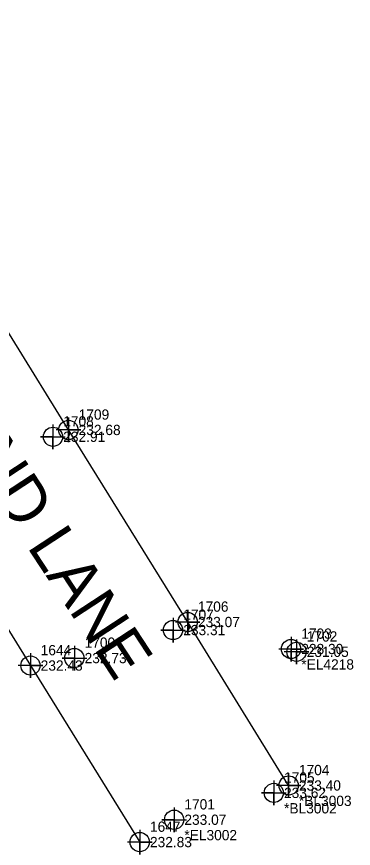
# Model space of a CAD drawing. Extents: x 2130621 to 2131998, y 642516 to 644503.
# Drawn here: x 2131203.6 to 2131285.6, y 643834.2 to 644036.8 of the extents above; entities that cross this region are included whole.
import ezdxf

# ---------------------------------------------------------------- set-up
doc = ezdxf.new("R2010")
doc.units = 0
for name, color, linetype in [('Exist Roads EOP', 7, 'Continuous'), ('Exist Roads EOP Other Cogo Comment', 7, 'Continuous'), ('Exist Roads EOP Other Cogo Elevation', 7, 'Continuous'), ('Exist Roads EOP Other Cogo Number', 7, 'Continuous'), ('Exist Roads EOP Other Cogo Point CELL', 7, 'Continuous'), ('Exist Roads EOT Cogo Comment', 7, 'Continuous'), ('Exist Roads EOT Cogo Elevation', 7, 'Continuous'), ('Exist Roads EOT Cogo Number', 7, 'Continuous'), ('Exist Roads EOT Cogo Point CELL', 7, 'Continuous'), ('Exist Roads EOT Text', 7, 'Continuous'), ('Exist Structure Minor Drop Inlet Cogo Elevation', 7, 'Continuous'), ('Exist Structure Minor Drop Inlet Cogo Number', 7, 'Continuous'), ('Exist Structure Minor Drop Inlet Cogo Point CELL', 7, 'Continuous'), ('Exist Structure Minor Pipes RCP 18 Inch Cogo Comment', 7, 'Continuous'), ('Exist Structure Minor Pipes RCP 18 Inch Cogo Elevation', 7, 'Continuous'), ('Exist Structure Minor Pipes RCP 18 Inch Cogo Number', 7, 'Continuous'), ('Exist Structure Minor Pipes RCP 18 Inch Cogo Point CELL', 7, 'Continuous'), ('Prop Horizontal Alignment', 7, 'Continuous')]:
    doc.layers.add(name, color=color, linetype=linetype)

msp = doc.modelspace()

# ---------------------------------------------------------------- linework, layer by layer
at = {"layer": 'Exist Roads EOP'}
for points in [[(2131269.83, 643849.54), (2131245.23, 643889.35), (2131216.18, 643936.13), (2131188.66, 643980.63), (2131160.56, 644026.02), (2131133.77, 644069.38), (2131106.56, 644113.29), (2131078.46, 644158.69), (2131052.15, 644201.1)], [(2131125, 644001.4), (2131151.48, 643966.59), (2131158.59, 643957.1), (2131179.44, 643923.18), (2131206.93, 643878.75), (2131233.55, 643835.75)]]:
    msp.add_lwpolyline(points, dxfattribs=at)
msp.add_spline([(2131166.25, 643216.7), (2131171.81, 643218.72), (2131182.37, 643223.97), (2131191.81, 643231.15), (2131200.5, 643239.7), (2131208.81, 643249.07), (2131216.07, 643259), (2131218.72, 643264.35), (2131220.54, 643270.1), (2131222.84, 643282.01), (2131224.36, 643293.92), (2131224.88, 643317.79), (2131222.06, 643367.67), (2131218.54, 643416.81), (2131214.32, 643466.35), (2131209.17, 643515.67), (2131202.79, 643565.15), (2131195.05, 643613.99), (2131186.4, 643662.48), (2131176.01, 643711.41), (2131164.62, 643759.89), (2131151.87, 643807.85), (2131137.86, 643855.41), (2131122.57, 643902.86), (2131105.96, 643949.49), (2131091.53, 643988.04)], degree=3, dxfattribs=at)
at = {"layer": 'Exist Roads EOP Other Cogo Point CELL'}
for points in [[(2131216.18, 643939.13), (2131216.18, 643933.13), (2131216.18, 643936.13), (2131219.18, 643936.13), (2131213.18, 643936.13)], [(2131245.23, 643892.35), (2131245.23, 643886.35), (2131245.23, 643889.35), (2131248.23, 643889.35), (2131242.23, 643889.35)], [(2131206.93, 643881.75), (2131206.93, 643875.75), (2131206.93, 643878.75), (2131209.93, 643878.75), (2131203.93, 643878.75)], [(2131269.83, 643852.54), (2131269.83, 643846.54), (2131269.83, 643849.54), (2131272.83, 643849.54), (2131266.83, 643849.54)], [(2131233.55, 643838.75), (2131233.55, 643832.75), (2131233.55, 643835.75), (2131236.55, 643835.75), (2131230.55, 643835.75)]]:
    msp.add_lwpolyline(points, dxfattribs=at)
for centre in [(2131216.18, 643936.13), (2131245.23, 643889.35), (2131206.93, 643878.75), (2131269.83, 643849.54), (2131233.55, 643835.75)]:
    msp.add_circle(centre, 2.34, dxfattribs=at)
at = {"layer": 'Exist Roads EOT Cogo Point CELL'}
for points in [[(2131212.42, 643937.47), (2131212.42, 643931.47), (2131212.42, 643934.47), (2131209.42, 643934.47), (2131215.42, 643934.47)], [(2131241.66, 643890.39), (2131241.66, 643884.39), (2131241.66, 643887.39), (2131238.66, 643887.39), (2131244.66, 643887.39)], [(2131217.63, 643883.57), (2131217.63, 643877.57), (2131217.63, 643880.57), (2131214.63, 643880.57), (2131220.63, 643880.57)], [(2131266.21, 643850.73), (2131266.21, 643844.73), (2131266.21, 643847.73), (2131263.21, 643847.73), (2131269.21, 643847.73)], [(2131241.93, 643844.19), (2131241.93, 643838.19), (2131241.93, 643841.19), (2131238.93, 643841.19), (2131244.93, 643841.19)]]:
    msp.add_lwpolyline(points, dxfattribs=at)
for centre in [(2131212.42, 643934.47), (2131241.66, 643887.39), (2131217.63, 643880.57), (2131266.21, 643847.73), (2131241.93, 643841.19)]:
    msp.add_circle(centre, 2.34, dxfattribs=at)
at = {"layer": 'Exist Structure Minor Drop Inlet Cogo Point CELL'}
msp.add_lwpolyline([(2131271.74, 643885.09), (2131271.74, 643879.09), (2131271.74, 643882.09), (2131274.74, 643882.09), (2131268.74, 643882.09)], dxfattribs=at)
msp.add_circle((2131271.74, 643882.09), 2.34, dxfattribs=at)
at = {"layer": 'Exist Structure Minor Pipes RCP 18 Inch Cogo Point CELL'}
msp.add_lwpolyline([(2131270.41, 643885.77), (2131270.41, 643879.77), (2131270.41, 643882.77), (2131273.41, 643882.77), (2131267.41, 643882.77)], dxfattribs=at)
msp.add_circle((2131270.41, 643882.77), 2.34, dxfattribs=at)
at = {"layer": 'Prop Horizontal Alignment'}
msp.add_arc((2129448.47, 643307.66), 1788.96, 4.14306, 22.49968, dxfattribs=at)

# ---------------------------------------------------------------- texts
at = {"layer": 'Exist Roads EOP Other Cogo Comment'}
msp.add_text('*BL3003', height=2.5, dxfattribs=at).set_placement((2131272.33, 643844.54))
at = {"layer": 'Exist Roads EOP Other Cogo Elevation'}
for s, p in [('232.68', (2131218.68, 643934.88)), ('233.07', (2131247.73, 643888.1)), ('232.43', (2131209.43, 643877.5)), ('233.40', (2131272.33, 643848.29)), ('232.83', (2131236.05, 643834.5))]:
    msp.add_text(s, height=2.5, dxfattribs=at).set_placement(p)
at = {"layer": 'Exist Roads EOP Other Cogo Number'}
for s, p in [('1709', (2131218.68, 643938.63)), ('1706', (2131247.73, 643891.85)), ('1644', (2131209.43, 643881.25)), ('1704', (2131272.33, 643852.04)), ('1647', (2131236.05, 643838.25))]:
    msp.add_text(s, height=2.5, dxfattribs=at).set_placement(p)
at = {"layer": 'Exist Roads EOT Cogo Comment'}
for s, p in [('*BL3002', (2131268.71, 643842.73)), ('*EL3002', (2131244.43, 643836.19))]:
    msp.add_text(s, height=2.5, dxfattribs=at).set_placement(p)
at = {"layer": 'Exist Roads EOT Cogo Elevation'}
for s, p in [('232.91', (2131214.92, 643933.22)), ('233.31', (2131244.16, 643886.14)), ('232.73', (2131220.13, 643879.32)), ('233.62', (2131268.71, 643846.48)), ('233.07', (2131244.43, 643839.94))]:
    msp.add_text(s, height=2.5, dxfattribs=at).set_placement(p)
at = {"layer": 'Exist Roads EOT Cogo Number'}
for s, p in [('1708', (2131214.92, 643936.97)), ('1707', (2131244.16, 643889.89)), ('1700', (2131220.13, 643883.07)), ('1705', (2131268.71, 643850.23)), ('1701', (2131244.43, 643843.69))]:
    msp.add_text(s, height=2.5, dxfattribs=at).set_placement(p)
at = {"layer": 'Exist Roads EOT Text'}
msp.add_text('I-40 EAST BOUND LANE', height=11.3735, rotation=303.2392, dxfattribs=at).set_placement((2131132.75, 644019.45))
at = {"layer": 'Exist Structure Minor Drop Inlet Cogo Elevation'}
msp.add_text('231.05', height=2.5, dxfattribs=at).set_placement((2131274.24, 643880.84))
at = {"layer": 'Exist Structure Minor Drop Inlet Cogo Number'}
msp.add_text('1702', height=2.5, dxfattribs=at).set_placement((2131274.24, 643884.59))
at = {"layer": 'Exist Structure Minor Pipes RCP 18 Inch Cogo Comment'}
msp.add_text('*EL4218', height=2.5, dxfattribs=at).set_placement((2131272.91, 643877.77))
at = {"layer": 'Exist Structure Minor Pipes RCP 18 Inch Cogo Elevation'}
msp.add_text('228.30', height=2.5, dxfattribs=at).set_placement((2131272.91, 643881.52))
at = {"layer": 'Exist Structure Minor Pipes RCP 18 Inch Cogo Number'}
msp.add_text('1703', height=2.5, dxfattribs=at).set_placement((2131272.91, 643885.27))

doc.saveas('drawing.dxf')
